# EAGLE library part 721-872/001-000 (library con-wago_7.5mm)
Serie 721, Stiftleiste mit abgewinkelten Einlötstiften / Series 721, Male connector with angled solder pins Polzahl / Pole No.: 12 Rastermaß / Pitch: 7.5 mm Bemessungsspannung / Rated Voltage: 630 V Nennstrom / Nominal Current: 16 A Lötstiftlänge: / Solder Pin Length: 3.8 mm Farbe / Color: lichtgrau / light gray Stand: 01.01.2012. Die jeweils aktuellen Daten zu diesem Artikel finden Sie in unserem Produktkatalog, den Sie unter www.wago.com einsehen können. As of: 01/01/2012. Please find the newest data for this article in our product catalogue, which can be viewed under www.wago.com.
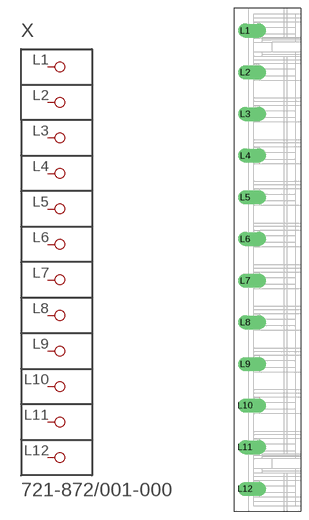
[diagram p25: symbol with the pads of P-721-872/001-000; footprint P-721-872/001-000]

Designator prefix X

## 721-872/001-000  [P-721-872/001-000]
L1  P1
L2  P2
L3  P3
L4  P4
L5  P5
L6  P6
L7  P7
L8  P8
L9  P9
L10  P10
L11  P11
L12  P12

## Footprint P-721-872/001-000 (pad centres in mm)
drill 1.7 offset: L1 -4,41.25; L2 -4,33.75; L3 -4,26.25; L4 -4,18.75; L5 -4,11.25; L6 -4,3.75; L7 -4,-3.75; L8 -4,-11.25; L9 -4,-18.75; L10 -4,-26.25; L11 -4,-33.75; L12 -4,-41.25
